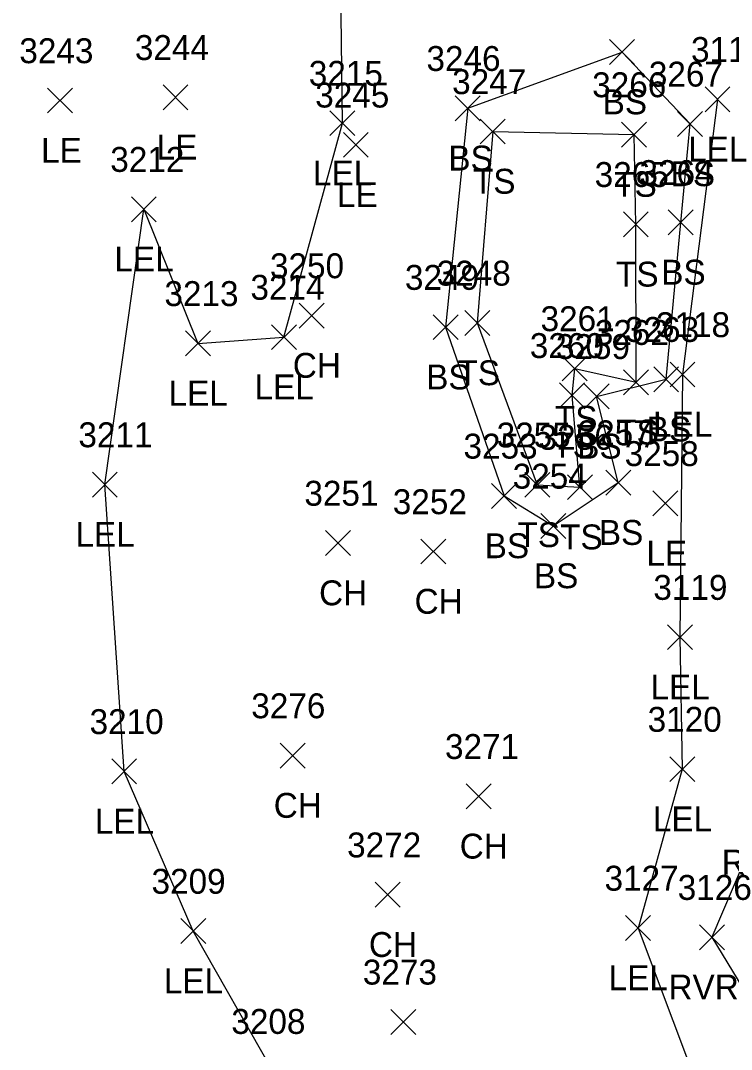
# Model space of a CAD drawing. Extents: x 1461855 to 1464118, y 556196 to 557441.
# Drawn here: x 1462058.9 to 1462115.9, y 556667.3 to 556749.9 of the extents above; entities that cross this region are included whole.
import ezdxf

# ---------------------------------------------------------------- set-up
doc = ezdxf.new("R2010")
doc.units = 0
for name, color, linetype in [('L_A', 7, 'Continuous'), ('L_I', 7, 'Continuous'), ('L_TIC', 7, 'Continuous'), ('LARO', 7, 'Continuous'), ('LAWE', 7, 'Continuous'), ('LELB', 7, 'Continuous')]:
    doc.layers.add(name, color=color, linetype=linetype)

msp = doc.modelspace()

# ---------------------------------------------------------------- linework, layer by layer
at = {"layer": 'L_TIC'}
for points in [[(1462106.155, 556746.413), (1462108.155, 556748.413)], [(1462108.155, 556746.413), (1462106.155, 556748.413)], [(1462106.155, 556746.413), (1462108.155, 556748.413)], [(1462108.155, 556746.413), (1462106.155, 556748.413)], [(1462061.024, 556742.52), (1462063.024, 556744.52)], [(1462063.024, 556742.52), (1462061.024, 556744.52)], [(1462070.301, 556742.776), (1462072.301, 556744.776)], [(1462072.301, 556742.776), (1462070.301, 556744.776)], [(1462113.819, 556742.616), (1462115.819, 556744.616)], [(1462115.819, 556742.616), (1462113.819, 556744.616)], [(1462093.766, 556741.897), (1462095.766, 556743.897)], [(1462095.766, 556741.897), (1462093.766, 556743.897)], [(1462093.766, 556741.897), (1462095.766, 556743.897)], [(1462095.766, 556741.897), (1462093.766, 556743.897)], [(1462083.698, 556740.701), (1462085.698, 556742.701)], [(1462085.698, 556740.701), (1462083.698, 556742.701)], [(1462111.612, 556740.64), (1462113.612, 556742.64)], [(1462113.612, 556740.64), (1462111.612, 556742.64)], [(1462095.773, 556740.034), (1462097.773, 556742.034)], [(1462097.773, 556740.034), (1462095.773, 556742.034)], [(1462095.773, 556740.034), (1462097.773, 556742.034)], [(1462097.773, 556740.034), (1462095.773, 556742.034)], [(1462107.117, 556739.786), (1462109.117, 556741.786)], [(1462109.117, 556739.786), (1462107.117, 556741.786)], [(1462107.117, 556739.786), (1462109.117, 556741.786)], [(1462109.117, 556739.786), (1462107.117, 556741.786)], [(1462084.78, 556738.957), (1462086.78, 556740.957)], [(1462086.78, 556738.957), (1462084.78, 556740.957)], [(1462067.76, 556733.788), (1462069.76, 556735.788)], [(1462069.76, 556733.788), (1462067.76, 556735.788)], [(1462107.262, 556732.574), (1462109.262, 556734.574)], [(1462109.262, 556732.574), (1462107.262, 556734.574)], [(1462110.86, 556732.73), (1462112.86, 556734.73)], [(1462112.86, 556732.73), (1462110.86, 556734.73)], [(1462081.234, 556725.245), (1462083.234, 556727.245)], [(1462083.234, 556725.245), (1462081.234, 556727.245)], [(1462091.99, 556724.312), (1462093.99, 556726.312)], [(1462093.99, 556724.312), (1462091.99, 556726.312)], [(1462094.532, 556724.652), (1462096.532, 556726.652)], [(1462096.532, 556724.652), (1462094.532, 556726.652)], [(1462079.013, 556723.514), (1462081.013, 556725.514)], [(1462081.013, 556723.514), (1462079.013, 556725.514)], [(1462072.108, 556723.01), (1462074.108, 556725.01)], [(1462074.108, 556723.01), (1462072.108, 556725.01)], [(1462102.353, 556720.991), (1462104.353, 556722.991)], [(1462104.353, 556720.991), (1462102.353, 556722.991)], [(1462107.274, 556719.887), (1462109.274, 556721.887)], [(1462109.274, 556719.887), (1462107.274, 556721.887)], [(1462109.696, 556720.129), (1462111.696, 556722.129)], [(1462111.696, 556720.129), (1462109.696, 556722.129)], [(1462111.004, 556720.512), (1462113.004, 556722.512)], [(1462113.004, 556720.512), (1462111.004, 556722.512)], [(1462102.142, 556718.833), (1462104.142, 556720.833)], [(1462104.142, 556718.833), (1462102.142, 556720.833)], [(1462104.115, 556718.755), (1462106.115, 556720.755)], [(1462106.115, 556718.755), (1462104.115, 556720.755)], [(1462064.633, 556711.668), (1462066.633, 556713.668)], [(1462066.633, 556711.668), (1462064.633, 556713.668)], [(1462099.346, 556711.648), (1462101.346, 556713.648)], [(1462101.346, 556711.648), (1462099.346, 556713.648)], [(1462105.849, 556711.823), (1462107.849, 556713.823)], [(1462107.849, 556711.823), (1462105.849, 556713.823)], [(1462096.684, 556710.755), (1462098.684, 556712.755)], [(1462098.684, 556710.755), (1462096.684, 556712.755)], [(1462102.77, 556711.463), (1462104.77, 556713.463)], [(1462104.77, 556711.463), (1462102.77, 556713.463)], [(1462109.623, 556710.156), (1462111.623, 556712.156)], [(1462111.623, 556710.156), (1462109.623, 556712.156)], [(1462100.636, 556708.343), (1462102.636, 556710.343)], [(1462102.636, 556708.343), (1462100.636, 556710.343)], [(1462083.342, 556706.97), (1462085.342, 556708.97)], [(1462085.342, 556706.97), (1462083.342, 556708.97)], [(1462091.006, 556706.29), (1462093.006, 556708.29)], [(1462093.006, 556706.29), (1462091.006, 556708.29)], [(1462110.801, 556699.408), (1462112.801, 556701.408)], [(1462112.801, 556699.408), (1462110.801, 556701.408)], [(1462079.701, 556689.897), (1462081.701, 556691.897)], [(1462081.701, 556689.897), (1462079.701, 556691.897)], [(1462066.184, 556688.624), (1462068.184, 556690.624)], [(1462068.184, 556688.624), (1462066.184, 556690.624)], [(1462110.988, 556688.807), (1462112.988, 556690.807)], [(1462112.988, 556688.807), (1462110.988, 556690.807)], [(1462094.633, 556686.623), (1462096.633, 556688.623)], [(1462096.633, 556686.623), (1462094.633, 556688.623)], [(1462087.34, 556678.718), (1462089.34, 556680.718)], [(1462089.34, 556678.718), (1462087.34, 556680.718)], [(1462107.44, 556676.046), (1462109.44, 556678.046)], [(1462109.44, 556676.046), (1462107.44, 556678.046)], [(1462071.726, 556675.797), (1462073.726, 556677.797)], [(1462073.726, 556675.797), (1462071.726, 556677.797)], [(1462113.371, 556675.303), (1462115.371, 556677.303)], [(1462115.371, 556675.303), (1462113.371, 556677.303)], [(1462088.603, 556668.502), (1462090.603, 556670.502)], [(1462090.603, 556668.502), (1462088.603, 556670.502)]]:
    msp.add_lwpolyline(points, dxfattribs=at)
at = {"layer": 'LARO'}
for points in [[(1462079.126, 556665.539), (1462072.726, 556676.797), (1462067.184, 556689.624), (1462065.633, 556712.668), (1462068.76, 556734.788), (1462073.108, 556724.01), (1462080.013, 556724.514), (1462084.698, 556741.701), (1462084.511, 556756.906), (1462096.208, 556759.141), (1462103.715, 556778.381), (1462105.086, 556802.615), (1462102.994, 556815.774)], [(1462114.819, 556743.616), (1462112.004, 556721.512), (1462111.801, 556700.408), (1462111.988, 556689.807), (1462108.44, 556677.046), (1462114.001, 556662.205)]]:
    msp.add_lwpolyline(points, dxfattribs=at)
at = {"layer": 'LAWE'}
msp.add_lwpolyline([(1462120.691, 556737.434), (1462122.423, 556720.718), (1462119.992, 556701.198), (1462119.681, 556688.809), (1462118.64, 556686.34), (1462114.371, 556676.303), (1462125.062, 556658.7), (1462126.988, 556641.518), (1462131.288, 556633.529), (1462137.745, 556624.648), (1462141.077, 556615.301), (1462145.141, 556602.946), (1462161.881, 556553.375), (1462138.756, 556543.397)], dxfattribs=at)
at = {"layer": 'LELB'}
for points in [[(1462094.766, 556742.897), (1462092.99, 556725.312), (1462097.684, 556711.755), (1462101.636, 556709.343), (1462106.849, 556712.823), (1462105.115, 556719.755), (1462110.696, 556721.129), (1462111.86, 556733.73), (1462112.612, 556741.64), (1462107.155, 556747.413)], [(1462094.766, 556742.897), (1462107.155, 556747.413)], [(1462096.773, 556741.034), (1462095.532, 556725.652), (1462100.346, 556712.648), (1462103.77, 556712.463), (1462103.142, 556719.833), (1462103.353, 556721.991), (1462108.274, 556720.887), (1462108.262, 556733.574), (1462108.117, 556740.786)], [(1462096.773, 556741.034), (1462108.117, 556740.786)]]:
    msp.add_lwpolyline(points, dxfattribs=at)

# ---------------------------------------------------------------- texts
at = {"layer": 'L_A'}
for s, p in [('BS', (1462105.596, 556742.413)), ('BS', (1462105.596, 556742.413)), ('LE', (1462069.789, 556738.776)), ('LE', (1462060.512, 556738.52)), ('BS', (1462093.207, 556737.897)), ('BS', (1462093.207, 556737.897)), ('LEL', (1462112.457, 556738.616)), ('LEL', (1462082.336, 556736.701)), ('BS', (1462111.053, 556736.64)), ('TS', (1462095.183, 556736.034)), ('TS', (1462095.183, 556736.034)), ('TS', (1462106.526, 556735.786)), ('TS', (1462106.526, 556735.786)), ('LE', (1462084.268, 556734.957)), ('LEL', (1462066.397, 556729.788)), ('TS', (1462106.672, 556728.574)), ('BS', (1462110.301, 556728.73)), ('CH', (1462080.722, 556721.245)), ('TS', (1462093.941, 556720.652)), ('BS', (1462091.43, 556720.312)), ('LEL', (1462070.746, 556719.01)), ('LEL', (1462077.65, 556719.514)), ('TS', (1462101.762, 556716.991)), ('LEL', (1462109.642, 556716.512)), ('TS', (1462106.683, 556715.887)), ('BS', (1462109.137, 556716.129)), ('TS', (1462101.551, 556714.833)), ('BS', (1462103.556, 556714.755)), ('LEL', (1462063.27, 556707.668)), ('TS', (1462098.755, 556707.648)), ('TS', (1462102.18, 556707.463)), ('BS', (1462105.29, 556707.823)), ('BS', (1462096.125, 556706.755)), ('LE', (1462109.111, 556706.156)), ('BS', (1462100.077, 556704.343)), ('CH', (1462082.83, 556702.97)), ('CH', (1462090.495, 556702.29)), ('LEL', (1462109.439, 556695.408)), ('CH', (1462079.189, 556685.897)), ('LEL', (1462064.822, 556684.624)), ('LEL', (1462109.626, 556684.807)), ('CH', (1462094.121, 556682.623)), ('RVRR', (1462115.152, 556681.34)), ('CH', (1462086.829, 556674.718)), ('LEL', (1462106.077, 556672.046)), ('LEL', (1462070.363, 556671.797)), ('RVRR', (1462110.882, 556671.303))]:
    msp.add_text(s, height=2, dxfattribs=at).set_placement(p)
at = {"layer": 'L_I'}
for s, p in [('3243', (1462058.764, 556746.52)), ('3244', (1462068.041, 556746.776)), ('3117', (1462112.693, 556746.616)), ('3246', (1462091.451, 556745.897)), ('3246', (1462091.451, 556745.897)), ('3215', (1462082.005, 556744.701)), ('3267', (1462109.305, 556744.64)), ('3247', (1462093.513, 556744.034)), ('3247', (1462093.513, 556744.034)), ('3266', (1462104.755, 556743.786)), ('3266', (1462104.755, 556743.786)), ('3245', (1462082.52, 556742.957)), ('3212', (1462066.067, 556737.788)), ('3265', (1462104.955, 556736.574)), ('3264', (1462108.553, 556736.73)), ('3250', (1462078.888, 556729.245)), ('3249', (1462089.722, 556728.312)), ('3248', (1462092.272, 556728.652)), ('3214', (1462077.32, 556727.514)), ('3213', (1462070.415, 556727.01)), ('3261', (1462100.612, 556724.991)), ('3262', (1462104.967, 556723.887)), ('3263', (1462107.389, 556724.129)), ('3118', (1462109.878, 556724.512)), ('3260', (1462099.748, 556722.833)), ('3259', (1462101.847, 556722.755)), ('3211', (1462063.507, 556715.668)), ('3255', (1462097.086, 556715.648)), ('3257', (1462103.59, 556715.823)), ('3253', (1462094.424, 556714.755)), ('3256', (1462100.455, 556715.463)), ('3258', (1462107.363, 556714.156)), ('3254', (1462098.376, 556712.343)), ('3251', (1462081.649, 556710.97)), ('3252', (1462088.747, 556710.29)), ('3119', (1462109.667, 556703.408)), ('3276', (1462077.386, 556693.897)), ('3210', (1462064.404, 556692.624)), ('3120', (1462109.209, 556692.807)), ('3271', (1462092.94, 556690.623)), ('3272', (1462085.081, 556682.718)), ('3127', (1462105.747, 556680.046)), ('3209', (1462069.379, 556679.797)), ('3126', (1462111.623, 556679.303)), ('3273', (1462086.343, 556672.502)), ('3208', (1462075.787, 556668.539))]:
    msp.add_text(s, height=2, dxfattribs=at).set_placement(p)

doc.saveas('drawing.dxf')
